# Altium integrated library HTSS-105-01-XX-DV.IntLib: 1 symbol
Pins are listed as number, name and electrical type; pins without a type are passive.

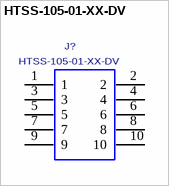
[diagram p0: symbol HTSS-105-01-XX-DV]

## HTSS-105-01-XX-DV
designator J?
HIGH TEMP TOP SHROUD; MANUFACTURER: SAMTEC
footprint HTSS-105-01-XX-DV
pins: 1, 2, 3, 4, 5, 6, 7, 8, 9, 10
